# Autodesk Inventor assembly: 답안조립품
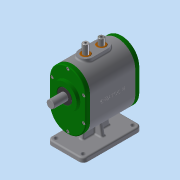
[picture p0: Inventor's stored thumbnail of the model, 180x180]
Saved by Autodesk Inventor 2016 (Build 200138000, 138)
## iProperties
Created: 2018-10
Part Number: 답안조립품
Material: 일반
Document SubType Name: Assembly
Designer: 3sil_cad0123
Mass: 2684.67 g
Surface Area: 2130.56 cm^2
Volume: 748.302 cm^3
Density: 3.58769 g/cm^3
Author: 3sil_cad0123
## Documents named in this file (15)
- C:\Users\3sil_cad0123\Desktop\381008V1007\답안조립품.iam
- C:\Users\3sil_cad0123\Desktop\381008V1007\본체.ipt
- C:\Users\3sil_cad0123\Desktop\381008V1007\가변 스프링1.ipt
- C:\Users\3sil_cad0123\Desktop\381008V1007\가변 스프링2.ipt
- C:\Users\3sil_cad0123\Desktop\381008V1007\뒤커버.ipt
- C:\Users\3sil_cad0123\Desktop\381008V1007\메인축.ipt
- C:\Users\3sil_cad0123\Desktop\381008V1007\베어링 608.ipt
- C:\Users\3sil_cad0123\Desktop\381008V1007\베어링 6003.ipt
- C:\Users\3sil_cad0123\Desktop\381008V1007\볼트 M4.ipt
- C:\Users\3sil_cad0123\Desktop\381008V1007\부시.ipt
- C:\Users\3sil_cad0123\Desktop\381008V1007\서브축.ipt
- C:\Users\3sil_cad0123\Desktop\381008V1007\슬라이더.ipt
- C:\Users\3sil_cad0123\Desktop\381008V1007\앞커버.ipt
- C:\Users\3sil_cad0123\Desktop\381008V1007\오일실 8 22 7.ipt
- C:\Users\3sil_cad0123\Desktop\381008V1007\오일실 17 32 8.ipt
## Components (2 placed, 2 different names)
1. 가변 스프링1:1
2. 가변 스프링2:1
